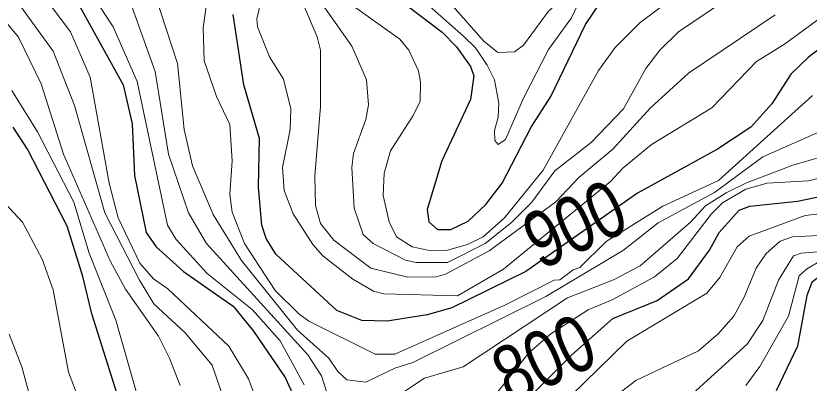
# Model space of a CAD drawing. Extents: x 577 to 602.9, y 7483.8 to 7511.6.
# Drawn here: x 583.887 to 585.016, y 7484.708 to 7485.231 of the extents above; entities that cross this region are included whole.
import ezdxf
from ezdxf.enums import TextEntityAlignment as Align

# ---------------------------------------------------------------- set-up
doc = ezdxf.new("R2010")
doc.units = 0
doc.header["$LTSCALE"] = 0.032
doc.layers.add('1', color=7, linetype='Continuous', lineweight=25)
doc.layers.add('2', color=7, linetype='Continuous', lineweight=13)
doc.layers.add('61', color=7, linetype='Continuous')

msp = doc.modelspace()

# ---------------------------------------------------------------- linework, layer by layer
at = {"layer": '1'}
for points in [[(585.9245, 7485.6421), (585.8728, 7485.5904), (585.8386, 7485.5506), (585.818, 7485.5109), (585.7639, 7485.4266), (585.7098, 7485.328), (585.6709, 7485.2389), (585.639, 7485.1817), (585.5905, 7485.134), (585.5476, 7485.1045), (585.5237, 7485.0958), (585.4673, 7485.0855), (585.414, 7485.064), (585.3814, 7485.0433), (585.3337, 7484.9837), (585.3178, 7484.9686), (585.2709, 7484.9336), (585.2256, 7484.9073), (585.1564, 7484.8835), (585.0371, 7484.8652), (585.0196, 7484.8509), (585.0124, 7484.8326), (584.9989, 7484.7602), (584.9687, 7484.6966)], [(583.8825, 7485.3868), (583.8881, 7485.3654), (583.9739, 7485.2516), (584.0399, 7485.1324), (584.0527, 7485.0767), (584.0559, 7485.0035), (584.0726, 7484.9224), (584.0869, 7484.9018), (584.1258, 7484.8668), (584.1966, 7484.8175), (584.2252, 7484.7817), (584.2706, 7484.7157), (584.2785, 7484.6982), (584.2785, 7484.6537), (584.2682, 7484.6052), (584.2753, 7484.5781), (584.2857, 7484.5567), (584.3103, 7484.5304), (584.3238, 7484.5241), (584.3413, 7484.5249), (584.3962, 7484.5511), (584.4177, 7484.5678), (584.4375, 7484.5932), (584.4693, 7484.6211)], [(584.3962, 7485.2819), (584.4936, 7485.2072), (584.5139, 7485.1864), (584.5338, 7485.1586), (584.5385, 7485.1451), (584.5338, 7485.1117), (584.4932, 7485.0242), (584.4725, 7484.955), (584.4749, 7484.9376), (584.4868, 7484.9264), (584.5059, 7484.9264), (584.5306, 7484.9383), (584.556, 7484.9622), (584.5791, 7484.9924), (584.6204, 7485.0719), (584.6483, 7485.1157), (584.6976, 7485.2182), (584.7182, 7485.2493)], [(585.0522, 7485.2), (585.014, 7485.1713), (584.9894, 7485.1475), (584.9624, 7485.1053), (584.9329, 7485.0719), (584.8852, 7485.0409), (584.7715, 7484.9781), (584.6125, 7484.8668), (584.5075, 7484.8151), (584.4725, 7484.8048), (584.4153, 7484.796), (584.3795, 7484.7968), (584.3437, 7484.8111), (584.257, 7484.8914), (584.2435, 7484.9137), (584.2372, 7484.9328), (584.2324, 7484.9869), (584.234, 7485.056), (584.2117, 7485.1324), (584.1966, 7485.2326)], [(584.1966, 7484.2465), (584.2085, 7484.2935), (584.2085, 7484.3245), (584.1998, 7484.3436), (584.1863, 7484.3555), (584.1529, 7484.3682), (584.1274, 7484.3833), (584.1028, 7484.4088), (584.0813, 7484.4445), (584.0749, 7484.4724), (584.0749, 7484.5074), (584.059, 7484.5678), (584.0463, 7484.6457), (583.9954, 7484.8063), (583.9827, 7484.8596), (583.9604, 7484.9312), (583.904, 7485.0409), (583.8833, 7485.0719)], [(584.5918, 7484.6616), (584.678, 7484.7481), (584.7365, 7484.8), (584.7993, 7484.8254), (584.8439, 7484.8564), (584.8741, 7484.897), (584.8876, 7484.9224), (584.9162, 7484.9542), (584.9313, 7484.9598), (584.9989, 7484.967), (585.0379, 7484.9749)]]:
    msp.add_lwpolyline(points, dxfattribs=at)
at = {"layer": '2'}
for points in [[(583.8698, 7485.7335), (583.9072, 7485.6954), (583.9461, 7485.6437), (583.9771, 7485.5952), (583.9843, 7485.5785), (583.9962, 7485.5196), (584.0169, 7485.4807), (584.0392, 7485.4592), (584.1179, 7485.398), (584.1489, 7485.3797), (584.16, 7485.3669), (584.1672, 7485.351), (584.1696, 7485.3264), (584.1537, 7485.2135), (584.1552, 7485.1666), (584.1727, 7485.1157), (584.1918, 7485.0759), (584.195, 7485.0242), (584.1918, 7484.9765), (584.195, 7484.9511), (584.2125, 7484.9065), (584.2562, 7484.8397), (584.2896, 7484.8063)], [(583.8857, 7485.5427), (583.9262, 7485.5021), (583.9604, 7485.4552), (583.9636, 7485.4369), (583.9509, 7485.4067), (583.9541, 7485.3773), (583.9708, 7485.355), (584.0272, 7485.2962), (584.0455, 7485.2628), (584.0853, 7485.1515), (584.1044, 7485.0338), (584.133, 7484.9503), (584.1584, 7484.9065), (584.3027, 7484.7481), (584.3222, 7484.7181), (584.3397, 7484.6632)], [(584.2976, 7484.7054), (584.2634, 7484.7682), (584.2236, 7484.8127), (584.1592, 7484.8636), (584.1155, 7484.9121), (584.1028, 7484.9328), (584.0598, 7485.1371), (584.0256, 7485.2151), (583.9708, 7485.2994), (583.9254, 7485.3805), (583.9135, 7485.4194), (583.9135, 7485.4584), (583.9103, 7485.4727), (583.8825, 7485.4989)], [(585.0196, 7485.4791), (584.987, 7485.4409), (584.9512, 7485.4218), (584.9031, 7485.4108), (584.8776, 7485.4007), (584.8575, 7485.3922), (584.8094, 7485.3591), (584.7753, 7485.3506), (584.7633, 7485.3426), (584.6451, 7485.2373), (584.6093, 7485.1888), (584.5966, 7485.1793), (584.5727, 7485.1785), (584.5528, 7485.1944), (584.5051, 7485.2485), (584.4399, 7485.3081), (584.3914, 7485.3741)], [(584.3938, 7484.6648), (584.4685, 7484.7149), (584.5234, 7484.7308), (584.6721, 7484.8294), (584.7373, 7484.8549), (584.7755, 7484.8747), (584.8471, 7484.9368), (584.868, 7484.96), (584.8978, 7484.9787), (584.9263, 7484.9927), (584.9926, 7485.0179), (585.0713, 7485.0409), (585.1381, 7485.0823), (585.1826, 7485.1141), (585.2184, 7485.1491), (585.3154, 7485.2596), (585.3432, 7485.3145), (585.3591, 7485.3598), (585.3655, 7485.4003)], [(584.6562, 7484.625), (584.7691, 7484.7117), (584.8582, 7484.7539), (584.8868, 7484.7785), (584.9083, 7484.8032), (584.9234, 7484.8302), (584.9401, 7484.8716), (584.9544, 7484.8922), (584.9743, 7484.9097), (584.9918, 7484.9161), (585.0299, 7484.9177), (585.0816, 7484.9352), (585.2057, 7484.9869), (585.2605, 7485.0187), (585.2844, 7485.0393), (585.3162, 7485.0592), (585.3782, 7485.1141), (585.4132, 7485.1475), (585.4673, 7485.2095), (585.5214, 7485.2429), (585.5516, 7485.2779), (585.5707, 7485.3168), (585.5866, 7485.3701)], [(585.0228, 7485.3495), (585.0069, 7485.3399), (584.917, 7485.3049), (584.8868, 7485.2858), (584.8129, 7485.2493), (584.7747, 7485.2206), (584.7397, 7485.1856), (584.7158, 7485.153), (584.6371, 7485.0107), (584.5823, 7484.9431), (584.552, 7484.9161), (584.5298, 7484.9049), (584.5012, 7484.897), (584.4781, 7484.8962), (584.4511, 7484.9018)], [(584.3906, 7485.32), (584.5242, 7485.2015), (584.5409, 7485.1848), (584.5576, 7485.1602), (584.5679, 7485.1395), (584.5743, 7485.1061), (584.5735, 7485.0862), (584.5679, 7485.0672), (584.5687, 7485.0529), (584.5735, 7485.0473), (584.5838, 7485.0544), (584.6093, 7485.1133), (584.6451, 7485.1825), (584.6777, 7485.2278), (584.6952, 7485.2652)], [(584.2284, 7484.6871), (584.2181, 7484.7141), (584.1902, 7484.7602), (584.1036, 7484.8421), (584.0829, 7484.8564), (584.0638, 7484.8787), (584.0328, 7484.9431), (584.0201, 7484.9924), (583.993, 7485.1435), (583.9652, 7485.2079), (583.9406, 7485.2405), (583.8753, 7485.3041)], [(584.1211, 7484.7046), (584.1059, 7484.7435), (584.09, 7484.7745), (584.0431, 7484.8413), (584.0217, 7484.8819), (583.9549, 7485.0338), (583.9231, 7485.134), (583.8913, 7485.2), (583.8181, 7485.2882)], [(585.0458, 7485.2381), (584.9806, 7485.1904), (584.9409, 7485.1658), (584.8773, 7485.0998), (584.7914, 7485.0473), (584.7508, 7485.0139), (584.7333, 7484.9948), (584.5807, 7484.87), (584.5155, 7484.8318), (584.4105, 7484.835), (584.3962, 7484.8389), (584.3668, 7484.8556), (584.3238, 7484.889), (584.3095, 7484.9049), (584.2817, 7484.9487), (584.269, 7484.9821), (584.2666, 7485.0147), (584.2777, 7485.0688), (584.2785, 7485.0982), (584.2682, 7485.1403), (584.2483, 7485.1721), (584.2308, 7485.2151), (584.23, 7485.2262), (584.2459, 7485.2938)], [(584.9671, 7485.2318), (584.8439, 7485.1491), (584.7898, 7485.0998), (584.7365, 7485.0409), (584.688, 7485.0004), (584.6551, 7484.9657), (584.5605, 7484.896), (584.4985, 7484.8629), (584.4852, 7484.859), (584.4447, 7484.8588), (584.3922, 7484.8716), (584.3397, 7484.9113), (584.3206, 7484.9352), (584.3135, 7484.9606), (584.3127, 7485.0028), (584.3206, 7485.1014), (584.3206, 7485.1817), (584.3159, 7485.2008), (584.2769, 7485.2922)], [(583.8801, 7485.2636), (583.9406, 7485.1801), (583.9708, 7485.1029), (584.0137, 7484.9503), (584.063, 7484.8541), (584.0837, 7484.8207), (584.1282, 7484.7793), (584.1664, 7484.7332), (584.1918, 7484.66)], [(585.0387, 7485.0695), (584.9496, 7485.0298), (584.8812, 7484.9789), (584.8009, 7484.936), (584.7516, 7484.897), (584.6411, 7484.831), (584.4519, 7484.7372), (584.4264, 7484.7292), (584.3851, 7484.7093), (584.358, 7484.7125), (584.3453, 7484.7244), (584.3326, 7484.7435), (584.2881, 7484.7832), (584.2082, 7484.8825), (584.168, 7484.9479), (584.1386, 7485.0171), (584.1266, 7485.0688), (584.1171, 7485.1626), (584.0853, 7485.2604)], [(584.327, 7485.2421), (584.3652, 7485.1872), (584.3859, 7485.1395), (584.389, 7485.1037), (584.3851, 7485.0831), (584.3676, 7485.0346), (584.3652, 7485.0147), (584.3684, 7484.9566), (584.3811, 7484.9193), (584.3954, 7484.9065), (584.4415, 7484.8827), (584.4566, 7484.8795), (584.5012, 7484.8795), (584.5549, 7484.9066), (584.5924, 7484.9362), (584.6212, 7484.9654), (584.6538, 7485.0099), (584.7055, 7485.0505), (584.7516, 7485.0982), (584.7834, 7485.1554), (584.8033, 7485.1817), (584.8296, 7485.2079), (584.8868, 7485.2461)], [(584.4511, 7484.9018), (584.4288, 7484.9161), (584.4185, 7484.9376), (584.4097, 7484.9749), (584.4113, 7485.0067), (584.42, 7485.0385), (584.4526, 7485.0886), (584.4622, 7485.1093), (584.463, 7485.1363), (584.4598, 7485.1522), (584.4463, 7485.1817), (584.4336, 7485.1976), (584.3707, 7485.2421)], [(583.8817, 7485.1244), (583.9183, 7485.0656), (583.97, 7484.9654), (583.9914, 7484.893), (584.0296, 7484.7976), (584.063, 7484.6791)], [(584.2896, 7484.8063), (584.3039, 7484.796), (584.3986, 7484.7491), (584.4264, 7484.7491), (584.5838, 7484.8191), (584.653, 7484.8541), (584.661, 7484.8549), (584.6801, 7484.8692), (584.6896, 7484.8723), (584.7267, 7484.9095), (584.8073, 7484.9598), (584.8868, 7484.9964), (585.0204, 7485.1173)], [(584.9258, 7484.7046), (584.9457, 7484.7316), (584.9862, 7484.8032), (585.0013, 7484.8604), (585.0117, 7484.87), (585.0339, 7484.8835), (585.1572, 7484.9137), (585.2128, 7484.9407), (585.2661, 7484.9606), (585.3098, 7484.9861), (585.3476, 7485.0213), (585.3886, 7485.0759), (585.4172, 7485.091)], [(585.0403, 7485.002), (585.014, 7484.9956), (584.956, 7484.9924), (584.9258, 7484.9837), (584.8924, 7484.9646), (584.8765, 7484.9487)], [(583.8523, 7484.9845), (583.8968, 7484.9368), (583.9246, 7484.8843), (583.9406, 7484.8405), (583.962, 7484.7236), (584.0121, 7484.594), (584.0169, 7484.5662), (584.0145, 7484.4573), (584.0209, 7484.4255), (584.0352, 7484.3936), (584.0559, 7484.3626), (584.0749, 7484.3459), (584.1107, 7484.3284), (584.1481, 7484.3189), (584.1608, 7484.3022), (584.1664, 7484.2481), (584.191, 7484.1638), (584.195, 7484.105), (584.1894, 7484.0819), (584.1751, 7484.0549), (584.1354, 7484.0048), (584.1226, 7483.981), (584.1195, 7483.9404), (584.131, 7483.8893)], [(584.8765, 7484.9487), (584.828, 7484.8851), (584.7957, 7484.8593), (584.7365, 7484.8266), (584.7012, 7484.8121), (584.6481, 7484.7778), (584.6176, 7484.7516), (584.5648, 7484.6855)], [(585.0602, 7484.9519), (585.0101, 7484.9463), (584.9305, 7484.9169), (584.9131, 7484.9018), (584.8884, 7484.858), (584.8701, 7484.8358), (584.7564, 7484.7674), (584.6769, 7484.6895)], [(585.058, 7484.8972), (585.0045, 7484.893), (584.9934, 7484.889), (584.9719, 7484.8541), (584.9496, 7484.7968), (584.9274, 7484.7634), (584.8391, 7484.6831)], [(584.1007, 7483.8894), (584.0749, 7483.9563), (584.0718, 7483.9881), (584.0845, 7484.0191), (584.1322, 7484.0796), (584.1537, 7484.1241), (584.1473, 7484.1575), (584.1187, 7484.2195), (584.1203, 7484.2656), (584.1179, 7484.2744), (584.1115, 7484.2839), (584.1036, 7484.2879), (584.063, 7484.2863), (584.0527, 7484.2895), (584.0384, 7484.299), (584.0248, 7484.3165), (583.9819, 7484.4255), (583.9517, 7484.4787), (583.939, 7484.5304), (583.9318, 7484.5988), (583.896, 7484.7308), (583.8777, 7484.7777)]]:
    msp.add_lwpolyline(points, dxfattribs=at)

# ---------------------------------------------------------------- texts
at = {"layer": '61', "width": 0.8}
for s, rotation, p in [('900', 24.258, (584.6986, 7484.8978)), ('800', 24.679, (584.6549, 7484.7068))]:
    msp.add_text(s, height=0.08, rotation=rotation, dxfattribs=at).set_placement(p, align=Align.CENTER)

doc.saveas('drawing.dxf')
